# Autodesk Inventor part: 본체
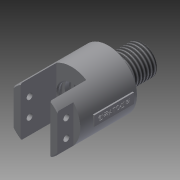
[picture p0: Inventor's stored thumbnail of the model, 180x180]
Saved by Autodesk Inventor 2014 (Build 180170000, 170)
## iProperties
Created: 2019-02
Part Number: 본체
Material: Generic
Document SubType Name: Modeling
Designer: OA55
Density: 1 g/cm^3
Appearance: Default
Author: OA55
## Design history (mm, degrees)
sketch "스케치1"
  geometry: C1 r 29 at (0, 0); 1 further point
  constraints: 1 centre point, 1 coincident
  dimensions: "d0" = 58 diameter of C1
extrude "돌출1" new body sketch "스케치1" stored distance "d1" = 74; taper "d2" = 0 deg
sketch "스케치2"
  geometry: L1 (29, -37)-(-29, -37) reference; L2 (-29, -37)-(-29, 37) reference; L3 (-29, 37)-(29, 37) reference; L4 (29, 37)-(29, -37) reference; L5 (15, 37)-(-15, 37); L6 (-15, 37)-(-15, 1); L7 (-15, 1)-(15, 1); L8 (15, 1)-(15, 37); L9 (22, 21)-(22, 37); L10 (0, 37)-(0, 0); L11 (22, 21)-(31.08, 21); L12 (31.08, 21)-(31.08, 37); L13 (31.08, 37)-(22, 37); L14 (-22, 21)-(-31.08, 21); L15 (-31.08, 21)-(-31.08, 37); L16 (-31.08, 37)-(-22, 37); L17 (-22, 21)-(-22, 37)
  constraints: 26 end point, 4 symmetric about line, 3 parallel, 2 perpendicular, 2 point on line, 1 collinear, 1 horizontal, 1 midpoint
  dimensions: "d6" = 36 distance of L7.end L5.start; "d7" = 30 distance of L6.end L7.end; "d8" = 15 distance from line of L10.end L8; "d10" = 22 distance between parallel lines of L10 L9; "d11" = 16 distance of L9.start L9.end; "d12" = 60.07958 distance between parallel lines of L2 L12
extrude "돌출2" cut sketch "스케치2" stored distance "d13" = 74; taper "d14" = 0 deg
sketch "스케치3"
  geometry: L1 (0, 0)-(0, 37.789) reference; L2 (16, 0)-(0, 0) reference; L3 (16, 37.789)-(16, 0) reference; L4 (73.898, 18.894)-(0, 18.894); C1 r 3 at (9, 27.894); C2 r 3 at (9, 9.894); 1 further point
  constraints: 2 centre point, 2 end point, 1 midpoint, 1 parallel, 1 symmetric about line, 1 other
  dimensions: "d15" = 6 diameter of C1; "d16" = 18 distance of C2.centre C1.centre; "d17" = 9 distance from line of L1 C1.centre; "d18" = 57.89803 distance from line of L4.start L3
extrude "돌출3" cut sketch "스케치3" distance "d19" = 50; taper "d20" = 0 deg
chamfer "모따기1" distance "d21" = 1; stored, may be unused: second distance "d22" = 2, angle "d23" = 45 deg
sketch "스케치4"
  geometry: C1 r 29 at (0, 0) reference; C2 r 13 at (0, 0); C3 r 15 at (0, 0)
  constraints: 2 centre point, 2 coincident
  dimensions: "d24" = 26 diameter of C2; "d25" = 30 diameter of C3
extrude "돌출7" join sketch "스케치4" distance "d43" = 5; taper "d44" = 0 deg
sketch "스케치7"
  geometry: C1 r 13 at (0, 0) reference; C2 r 15 at (0, 0)
  constraints: 1 centre point, 1 coincident
  dimensions: "d45" = 30 diameter of C2
extrude "돌출8" join sketch "스케치7" distance "d46" = 29; taper "d47" = 0 deg
feature "스레드2" dims "d48" = 10, "d49" = 0
sketch "스케치8"
  geometry: C1 r 15 at (0, 0) reference; C2 r 4 at (0, 0); 1 further point
  constraints: 2 coincident, 1 centre point
  dimensions: "d50" = 8 diameter of C2
hole "구멍2" sketch "스케치8" diameter "d51" = 11.835; stored, may be unused: countersink angle "d55" = 90 deg, drill point angle "d57" = 118 deg; dims "d52" = 18, "d53" = 4, "d54" = 2, "d56" = 22
extrude "돌출9" cut sketch "스케치8" stored distance "d58" = 31; taper "d59" = 0 deg
sketch "스케치9"
  geometry: L1 (0, 1.049)-(14, 1.049); L2 (14, -25.951)-(0, -25.951); L3 (0, -25.951)-(0, 1.049); L4 (0, 1.049)-(0, -25.951); L5 (0, -25.951)-(16, -25.951); L6 (16, -25.951)-(16, -18.951); L7 (16, -18.951)-(0, -18.951); L8 (17, -1.601)-(0, -1.601); L9 (17, -6.301)-(0, -6.301); L10 (20.309, -3.951)-(0, -3.951); L11 (20.309, -12.951)-(0, -12.951); L12 (17, -15.301)-(0, -15.301); L13 (17, -10.601)-(0, -10.601); L14 (17, -15.301)-(17, -10.601); L15 (17, -6.301)-(17, -1.601); L16 (14, 1.049)-(14, -1.601); L17 (14, -6.301)-(14, -10.601); L18 (14, -15.301)-(14, -18.951); 1 further point
  constraints: 36 end point, 11 parallel, 9 point on line, 7 perpendicular, 4 collinear, 1 horizontal
  dimensions: "d60" = 14 distance of L2.start L2.end; "d61" = 27 distance of L1.end L2.start; "d62" = 27 distance of L1.start L2.end (derived); "d63" = 16 distance of L2.end L5.end; "d64" = 7 distance of L5.end L6.end; "d67" = 4.7 distance between parallel lines of L9 L8; "d68" = 2.35 distance between parallel lines of L10 L9; "d69" = 9 distance between parallel lines of L11 L10; "d70" = 4.7 distance between parallel lines of L13 L12; "d71" = 2.35 distance between parallel lines of L12 L11; "d73" = 5 distance between parallel lines of L10 L1; "d74" = 3.65 distance between parallel lines of L12 L7; "d86" = 17 distance between parallel lines of L3 L14; "d105" = 20.30931 distance of L10.end L10.start; "d106" = 20.30931 distance of L11.start L11.end; "d107" = 17 distance from line of point (0, 0) L15; "d108" = 3.95062 distance from line of point (0, 0) L10; "d109" = 3.30931 distance from line of L11.start L15; "d110" = 17 distance from line of L9.end L15; "d113" = 0 distance between parallel lines of L14 L15; "d114" = 17 distance from line of L13.end L15; "d115" = 17 distance from line of L12.end L15
revolve "회전1" sketch "스케치9" stored, may be unused: angle "d116" = 90 deg
chamfer "모따기3" distance "d120" = 1; stored, may be unused: second distance "d121" = 2, angle "d122" = 45 deg
node "작업 평면1"
sketch "스케치10"
  geometry: L1 (5, 8)-(-5, 8); L2 (-5, 8)-(-5, -32); L3 (-5, -32)-(5, -32); L4 (5, -32)-(5, 8); L5 (-29, -37)-(29, -37) reference; 1 further point
  constraints: 8 end point, 2 parallel, 1 horizontal, 1 perpendicular
  dimensions: "d124" = 10 distance of L3.end L2.end; "d125" = 40 distance of L2.end L1.end; "d126" = 5 distance between parallel lines of L3 L5; "d127" = 5 distance from line of L4 point (0, 0)
extrude "돌출10" join sketch "스케치10" stored distance "d128" = 31; taper "d129" = 0 deg
sketch "스케치11"
  geometry: L1 (-8, 5)-(-8, -5) reference; L2 (-8, -5)-(32, -5) reference; 2 further points
  constraints: 1 other
  dimensions: "d130" = 20 distance from line of L1 point (12, 0); "d131" = 5 distance from line of L2 point (12, 0)
feature "엠보싱1" sketch "스케치11" dims "d132" = 0.5, "d133" = 0
chamfer "모따기4" distance "d134" = 1; stored, may be unused: second distance "d135" = 2, angle "d136" = 45 deg
chamfer "모따기5" distance "d137" = 1; stored, may be unused: second distance "d138" = 2, angle "d139" = 45 deg
fillet "모깎기1" dims "d140" = 0.8
node "솔리드1"
node "절단 모서리 투영1"
